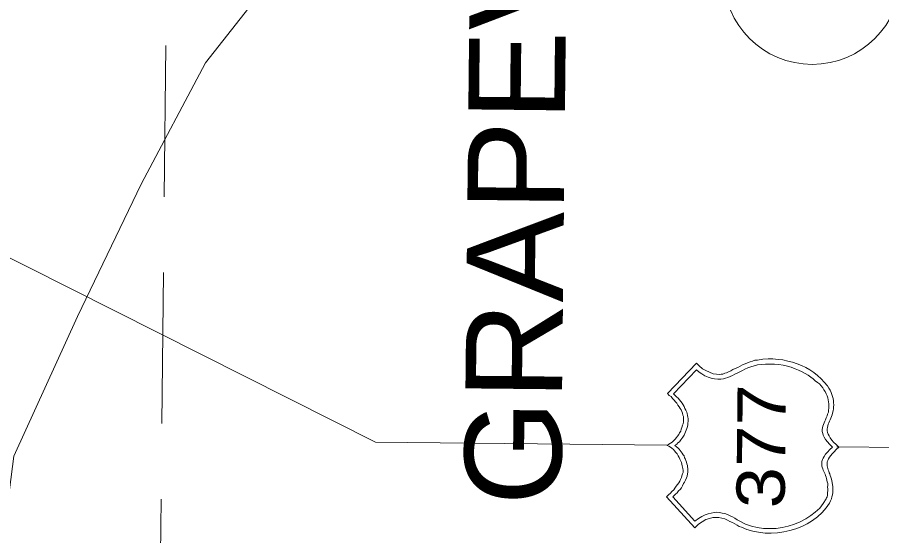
# Model space of a CAD drawing. Extents: x 2356576 to 2377878, y 6966390 to 6990634.
# Drawn here: x 2365706.5 to 2365828.3, y 6968964.1 to 6969037.2 of the extents above; entities that cross this region are included whole.
import ezdxf

# ---------------------------------------------------------------- set-up
doc = ezdxf.new("R2010")
doc.units = 0
doc.header["$LTSCALE"] = 7.1
doc.linetypes.add('MEDIUM_DASHED', pattern=[4.5, 3, -1.5])
doc.layers.add('19', color=7, linetype='Continuous', lineweight=13)
doc.layers.add('8', color=7, linetype='Continuous', lineweight=13)

msp = doc.modelspace()

# ---------------------------------------------------------------- linework, layer by layer
at = {"layer": '19', "linetype": 'MEDIUM_DASHED'}
msp.add_line((2365729.713, 6969256.812), (2365723.521, 6968659.188), dxfattribs=at)
at = {"layer": '19'}
for p, q in [((2365798.008, 6968976.87), (2365756.939, 6968977.295)), ((2365880.416, 6968976.016), (2365821.947, 6968976.622))]:
    msp.add_line(p, q, dxfattribs=at)
for points in [[(2365671.692, 6968744.602), (2365665.266, 6968758.801), (2365663.004, 6968777.877), (2365673.065, 6968799.226), (2365674.476, 6968813.793), (2365683.996, 6968831.843), (2365690.393, 6968844.289), (2365694.525, 6968855.019), (2365697.561, 6968870.136), (2365698.861, 6968882.424), (2365699.629, 6968898.62), (2365699.105, 6968917.587), (2365702.415, 6968941.706), (2365703.658, 6968957.414), (2365705.971, 6968975.299), (2365714.94, 6968994.979), (2365723.922, 6969013.667), (2365732.979, 6969030.738), (2365748.18, 6969050.082), (2365757.827, 6969063.09), (2365768.013, 6969079.038), (2365777.26, 6969088.122)], [(2365756.939, 6968977.295), (2365683.335, 6969014.359), (2365601.496, 6969032.7)], [(2365801.94, 6968965.216), (2365797.961, 6968969.606), (2365798.236, 6968969.843), (2365798.506, 6968970.08), (2365798.721, 6968970.35), (2365798.963, 6968970.587), (2365799.146, 6968970.825), (2365799.329, 6968971.092), (2365799.511, 6968971.302), (2365799.694, 6968971.568), (2365799.844, 6968971.806), (2365799.939, 6968972.045), (2365800.061, 6968972.316), (2365800.124, 6968972.555), (2365800.215, 6968972.823), (2365800.281, 6968973.034), (2365800.284, 6968973.302), (2365800.254, 6968973.574), (2365800.224, 6968973.754), (2365800.138, 6968973.963), (2365800.109, 6968974.204), (2365800.051, 6968974.444), (2365799.934, 6968974.69), (2365799.848, 6968974.898), (2365799.731, 6968975.14), (2365799.613, 6968975.381), (2365799.436, 6968975.623), (2365799.286, 6968975.836), (2365799.08, 6968976.046), (2365798.962, 6968976.26), (2365798.724, 6968976.442), (2365798.514, 6968976.592), (2365798.275, 6968976.715), (2365798.036, 6968976.837), (2365798.278, 6968976.987), (2365798.519, 6968977.164), (2365798.761, 6968977.31), (2365798.975, 6968977.52), (2365799.185, 6968977.697), (2365799.34, 6968977.936), (2365799.522, 6968978.142), (2365799.672, 6968978.38), (2365799.795, 6968978.619), (2365799.949, 6968978.858), (2365800.04, 6968979.129), (2365800.134, 6968979.368), (2365800.197, 6968979.667), (2365800.288, 6968979.874), (2365800.355, 6968980.173), (2365800.358, 6968980.445), (2365800.36, 6968980.653), (2365800.362, 6968980.893), (2365800.272, 6968981.106), (2365800.215, 6968981.375), (2365800.097, 6968981.588), (2365800.008, 6968981.829), (2365799.862, 6968982.039), (2365799.745, 6968982.28), (2365799.567, 6968982.494), (2365799.39, 6968982.764), (2365799.212, 6968982.977), (2365799.034, 6968983.219), (2365798.796, 6968983.43), (2365798.587, 6968983.704), (2365798.349, 6968983.886), (2365798.112, 6968984.129), (2365802.18, 6968988.435), (2365802.564, 6968988.043), (2365803.012, 6968987.646), (2365803.517, 6968987.373), (2365804.027, 6968987.156), (2365804.533, 6968986.943), (2365805.012, 6968986.878), (2365805.404, 6968986.841), (2365805.672, 6968986.871), (2365805.913, 6968986.896), (2365806.154, 6968987.014), (2365806.427, 6968987.071), (2365806.696, 6968987.22), (2365806.998, 6968987.365), (2365807.299, 6968987.514), (2365807.633, 6968987.658), (2365807.995, 6968987.835), (2365808.324, 6968988.011), (2365808.658, 6968988.188), (2365809.048, 6968988.336), (2365809.381, 6968988.48), (2365809.743, 6968988.629), (2365810.072, 6968988.713), (2365810.405, 6968988.83), (2365810.765, 6968988.858), (2365811.514, 6968988.97), (2365812.267, 6968989.023), (2365812.955, 6968989.015), (2365813.674, 6968988.948), (2365814.366, 6968988.881), (2365815.052, 6968988.722), (2365815.711, 6968988.567), (2365816.368, 6968988.348), (2365816.998, 6968988.101), (2365817.595, 6968987.795)], [(2365818.626, 6968986.224), (2365818.301, 6968986.468), (2365817.912, 6968986.744), (2365817.494, 6968986.956), (2365817.048, 6968987.201), (2365816.571, 6968987.418), (2365816.061, 6968987.631), (2365815.523, 6968987.849), (2365814.985, 6968988.002), (2365814.386, 6968988.129), (2365813.787, 6968988.227), (2365813.188, 6968988.293), (2365812.56, 6968988.299), (2365811.899, 6968988.274), (2365811.327, 6968988.22), (2365810.786, 6968988.166), (2365810.305, 6968988.051), (2365809.855, 6968987.907), (2365809.434, 6968987.76), (2365809.012, 6968987.584), (2365808.65, 6968987.408), (2365808.288, 6968987.204), (2365807.926, 6968986.995), (2365807.592, 6968986.851), (2365807.262, 6968986.674), (2365806.929, 6968986.526), (2365806.599, 6968986.381), (2365806.266, 6968986.293), (2365805.966, 6968986.208), (2365805.605, 6968986.151), (2365805.185, 6968986.156), (2365804.706, 6968986.221), (2365804.259, 6968986.313), (2365803.808, 6968986.438), (2365803.362, 6968986.623), (2365802.945, 6968986.899), (2365802.555, 6968987.171), (2365802.17, 6968987.475), (2365798.951, 6968984.088), (2365799.161, 6968983.878), (2365799.367, 6968983.696), (2365799.605, 6968983.481), (2365799.783, 6968983.272), (2365799.96, 6968983.03), (2365800.138, 6968982.788), (2365800.287, 6968982.546), (2365800.437, 6968982.305), (2365800.554, 6968982.031), (2365800.699, 6968981.79), (2365800.817, 6968981.521), (2365800.875, 6968981.308), (2365800.932, 6968981.04), (2365800.962, 6968980.827), (2365801.02, 6968980.647), (2365801.018, 6968980.439), (2365801.015, 6968980.227), (2365800.981, 6968979.959), (2365800.95, 6968979.719), (2365800.916, 6968979.48), (2365800.825, 6968979.209), (2365800.731, 6968979.001), (2365800.64, 6968978.73), (2365800.517, 6968978.492), (2365800.423, 6968978.285), (2365800.268, 6968977.986), (2365800.118, 6968977.808), (2365799.964, 6968977.597), (2365799.782, 6968977.359), (2365799.572, 6968977.213), (2365799.39, 6968977.003), (2365799.116, 6968976.826), (2365799.354, 6968976.644), (2365799.565, 6968976.493), (2365799.742, 6968976.28), (2365799.888, 6968976.098), (2365800.039, 6968975.916), (2365800.157, 6968975.735), (2365800.306, 6968975.494), (2365800.453, 6968975.344), (2365800.51, 6968975.104), (2365800.628, 6968974.89), (2365800.686, 6968974.682), (2365800.776, 6968974.469), (2365800.801, 6968974.256), (2365800.891, 6968974.016), (2365800.917, 6968973.807), (2365800.947, 6968973.595), (2365800.972, 6968973.355), (2365800.969, 6968973.055), (2365800.907, 6968972.815), (2365800.843, 6968972.516), (2365800.753, 6968972.249), (2365800.63, 6968971.95), (2365800.506, 6968971.651), (2365800.352, 6968971.441), (2365800.197, 6968971.143), (2365800.046, 6968970.876), (2365799.864, 6968970.638), (2365799.65, 6968970.428), (2365799.467, 6968970.162), (2365799.225, 6968969.953)], [(2365817.595, 6968987.795), (2365818.159, 6968987.461), (2365818.695, 6968987.096), (2365819.231, 6968986.698), (2365819.738, 6968986.213), (2365820.181, 6968985.728), (2365820.628, 6968985.216), (2365820.833, 6968984.914), (2365821.01, 6968984.612), (2365821.159, 6968984.31), (2365821.244, 6968984.009), (2365821.361, 6968983.736), (2365821.418, 6968983.435), (2365821.474, 6968983.107), (2365821.503, 6968982.835), (2365821.528, 6968982.534), (2365821.497, 6968982.235), (2365821.494, 6968981.967), (2365821.432, 6968981.695), (2365821.337, 6968981.396), (2365821.306, 6968981.156), (2365821.212, 6968980.917), (2365821.121, 6968980.678), (2365821.027, 6968980.439), (2365820.936, 6968980.232), (2365820.814, 6968980.021), (2365820.752, 6968979.814), (2365820.69, 6968979.603), (2365820.627, 6968979.363), (2365820.593, 6968979.156), (2365820.591, 6968978.916), (2365820.648, 6968978.675), (2365820.738, 6968978.434), (2365820.883, 6968978.161), (2365821.032, 6968977.919), (2365821.269, 6968977.589), (2365821.506, 6968977.286), (2365821.863, 6968976.982), (2365822.247, 6968976.586), (2365821.883, 6968976.262), (2365821.58, 6968975.933), (2365821.277, 6968975.668), (2365821.094, 6968975.398), (2365820.912, 6968975.16), (2365820.761, 6968974.922), (2365820.699, 6968974.714), (2365820.605, 6968974.503), (2365820.575, 6968974.324), (2365820.573, 6968974.112), (2365820.599, 6968973.963), (2365820.657, 6968973.751), (2365820.687, 6968973.57), (2365820.746, 6968973.39), (2365820.831, 6968973.181), (2365820.889, 6968972.968), (2365820.98, 6968972.819), (2365821.037, 6968972.579), (2365821.123, 6968972.338), (2365821.212, 6968972.097), (2365821.237, 6968971.825), (2365821.295, 6968971.584), (2365821.352, 6968971.283), (2365821.381, 6968971.043), (2365821.378, 6968970.743), (2365821.376, 6968970.503), (2365821.373, 6968970.203), (2365821.337, 6968969.876), (2365821.246, 6968969.604), (2365821.183, 6968969.305), (2365821.06, 6968969.006), (2365820.905, 6968968.708), (2365820.45, 6968968.025), (2365819.871, 6968967.371), (2365819.237, 6968966.777), (2365818.539, 6968966.244), (2365817.786, 6968965.772), (2365817.03, 6968965.388), (2365816.187, 6968965.097), (2365815.317, 6968964.838), (2365814.475, 6968964.666), (2365813.601, 6968964.523), (2365812.701, 6968964.473), (2365811.833, 6968964.482), (2365810.934, 6968964.583), (2365810.123, 6968964.739), (2365809.286, 6968964.988), (2365808.509, 6968965.296), (2365808.21, 6968965.419), (2365807.912, 6968965.574), (2365807.586, 6968965.758), (2365807.256, 6968965.969), (2365806.898, 6968966.125), (2365806.539, 6968966.309), (2365806.153, 6968966.493), (2365805.762, 6968966.557), (2365805.343, 6968966.649), (2365804.895, 6968966.654), (2365804.475, 6968966.658), (2365803.993, 6968966.515), (2365803.512, 6968966.368), (2365802.969, 6968966.074)], [(2365798.833, 6968969.597), (2365801.949, 6968966.144), (2365802.462, 6968966.531), (2365802.944, 6968966.794), (2365803.399, 6968967.029), (2365803.821, 6968967.205), (2365804.27, 6968967.292), (2365804.662, 6968967.376), (2365805.023, 6968967.432), (2365805.41, 6968967.368), (2365805.801, 6968967.276), (2365806.161, 6968967.213), (2365806.548, 6968967.089), (2365806.906, 6968966.905), (2365807.236, 6968966.749), (2365807.594, 6968966.566), (2365807.92, 6968966.354), (2365808.278, 6968966.139), (2365809.086, 6968965.742), (2365809.923, 6968965.462), (2365810.729, 6968965.245), (2365811.6, 6968965.144), (2365812.499, 6968965.107), (2365813.4, 6968965.126), (2365814.269, 6968965.269), (2365815.111, 6968965.468), (2365815.986, 6968965.731), (2365816.798, 6968966.082), (2365817.582, 6968966.462), (2365818.307, 6968966.935), (2365818.912, 6968967.441), (2365819.55, 6968968.002), (2365820.036, 6968968.629), (2365820.463, 6968969.285), (2365820.493, 6968969.432), (2365820.586, 6968969.583), (2365820.648, 6968969.791), (2365820.651, 6968970.031), (2365820.653, 6968970.211), (2365820.683, 6968970.45), (2365820.686, 6968970.69), (2365820.66, 6968970.931), (2365820.663, 6968971.203), (2365820.665, 6968971.443), (2365820.576, 6968971.684), (2365820.55, 6968971.924), (2365820.521, 6968972.164), (2365820.435, 6968972.373), (2365820.377, 6968972.586), (2365820.319, 6968972.766), (2365820.201, 6968972.975), (2365820.111, 6968973.156), (2365820.025, 6968973.337), (2365819.967, 6968973.518), (2365819.877, 6968973.759), (2365819.851, 6968973.911), (2365819.821, 6968974.119), (2365819.823, 6968974.331), (2365819.857, 6968974.543), (2365819.921, 6968974.842), (2365820.011, 6968975.05), (2365820.193, 6968975.288), (2365820.348, 6968975.586), (2365820.651, 6968975.883), (2365820.955, 6968976.24), (2365821.347, 6968976.568), (2365820.931, 6968976.992), (2365820.635, 6968977.355), (2365820.37, 6968977.658), (2365820.161, 6968977.988), (2365820.044, 6968978.289), (2365819.959, 6968978.53), (2365819.902, 6968978.803), (2365819.904, 6968979.071), (2365819.935, 6968979.311), (2365819.969, 6968979.522), (2365820.06, 6968979.761), (2365820.154, 6968980), (2365820.244, 6968980.239), (2365820.367, 6968980.446), (2365820.461, 6968980.717), (2365820.584, 6968980.984), (2365820.647, 6968981.255), (2365820.77, 6968981.522), (2365820.773, 6968981.822), (2365820.804, 6968982.094), (2365820.839, 6968982.393), (2365820.81, 6968982.694), (2365820.785, 6968982.962), (2365820.756, 6968983.262), (2365820.671, 6968983.535), (2365820.614, 6968983.836), (2365820.437, 6968984.106), (2365820.32, 6968984.407), (2365820.142, 6968984.649), (2365819.965, 6968984.951), (2365819.728, 6968985.225), (2365819.491, 6968985.495), (2365819.253, 6968985.71), (2365818.924, 6968985.953), (2365818.626, 6968986.224)], [(2365799.225, 6968969.953), (2365799.015, 6968969.775), (2365798.833, 6968969.597)], [(2365802.969, 6968966.074), (2365802.453, 6968965.719), (2365801.94, 6968965.216)]]:
    msp.add_lwpolyline(points, dxfattribs=at)
msp.add_circle((2365818.484, 6969043.016), 12.486, dxfattribs=at)
at = {"layer": '8', "linetype": 'MEDIUM_DASHED'}
msp.add_line((2365729.713, 6969256.812), (2365723.521, 6968659.188), dxfattribs=at)
at = {"layer": '8'}
for p, q in [((2365798.008, 6968976.87), (2365756.939, 6968977.295)), ((2365880.416, 6968976.016), (2365821.947, 6968976.622))]:
    msp.add_line(p, q, dxfattribs=at)
for points in [[(2365671.692, 6968744.602), (2365665.266, 6968758.801), (2365663.004, 6968777.877), (2365673.065, 6968799.226), (2365674.476, 6968813.793), (2365683.996, 6968831.843), (2365690.393, 6968844.289), (2365694.525, 6968855.019), (2365697.561, 6968870.136), (2365698.861, 6968882.424), (2365699.629, 6968898.62), (2365699.105, 6968917.587), (2365702.415, 6968941.706), (2365703.658, 6968957.414), (2365705.971, 6968975.299), (2365714.94, 6968994.979), (2365723.922, 6969013.667), (2365732.979, 6969030.738), (2365748.18, 6969050.082), (2365757.827, 6969063.09), (2365768.013, 6969079.038), (2365777.26, 6969088.122)], [(2365756.939, 6968977.295), (2365683.335, 6969014.359), (2365601.496, 6969032.7)], [(2365801.94, 6968965.216), (2365797.961, 6968969.606), (2365798.236, 6968969.843), (2365798.506, 6968970.08), (2365798.721, 6968970.35), (2365798.963, 6968970.587), (2365799.146, 6968970.825), (2365799.329, 6968971.092), (2365799.511, 6968971.302), (2365799.694, 6968971.568), (2365799.844, 6968971.806), (2365799.939, 6968972.045), (2365800.061, 6968972.316), (2365800.124, 6968972.555), (2365800.215, 6968972.823), (2365800.281, 6968973.034), (2365800.284, 6968973.302), (2365800.254, 6968973.574), (2365800.224, 6968973.754), (2365800.138, 6968973.963), (2365800.109, 6968974.204), (2365800.051, 6968974.444), (2365799.934, 6968974.69), (2365799.848, 6968974.898), (2365799.731, 6968975.14), (2365799.613, 6968975.381), (2365799.436, 6968975.623), (2365799.286, 6968975.836), (2365799.08, 6968976.046), (2365798.962, 6968976.26), (2365798.724, 6968976.442), (2365798.514, 6968976.592), (2365798.275, 6968976.715), (2365798.036, 6968976.837), (2365798.278, 6968976.987), (2365798.519, 6968977.164), (2365798.761, 6968977.31), (2365798.975, 6968977.52), (2365799.185, 6968977.697), (2365799.34, 6968977.936), (2365799.522, 6968978.142), (2365799.672, 6968978.38), (2365799.795, 6968978.619), (2365799.949, 6968978.858), (2365800.04, 6968979.129), (2365800.134, 6968979.368), (2365800.197, 6968979.667), (2365800.288, 6968979.874), (2365800.355, 6968980.173), (2365800.358, 6968980.445), (2365800.36, 6968980.653), (2365800.362, 6968980.893), (2365800.272, 6968981.106), (2365800.215, 6968981.375), (2365800.097, 6968981.588), (2365800.008, 6968981.829), (2365799.862, 6968982.039), (2365799.745, 6968982.28), (2365799.567, 6968982.494), (2365799.39, 6968982.764), (2365799.212, 6968982.977), (2365799.034, 6968983.219), (2365798.796, 6968983.43), (2365798.587, 6968983.704), (2365798.349, 6968983.886), (2365798.112, 6968984.129), (2365802.18, 6968988.435), (2365802.564, 6968988.043), (2365803.012, 6968987.646), (2365803.517, 6968987.373), (2365804.027, 6968987.156), (2365804.533, 6968986.943), (2365805.012, 6968986.878), (2365805.404, 6968986.841), (2365805.672, 6968986.871), (2365805.913, 6968986.896), (2365806.154, 6968987.014), (2365806.427, 6968987.071), (2365806.696, 6968987.22), (2365806.998, 6968987.365), (2365807.299, 6968987.514), (2365807.633, 6968987.658), (2365807.995, 6968987.835), (2365808.324, 6968988.011), (2365808.658, 6968988.188), (2365809.048, 6968988.336), (2365809.381, 6968988.48), (2365809.743, 6968988.629), (2365810.072, 6968988.713), (2365810.405, 6968988.83), (2365810.765, 6968988.858), (2365811.514, 6968988.97), (2365812.267, 6968989.023), (2365812.955, 6968989.015), (2365813.674, 6968988.948), (2365814.366, 6968988.881), (2365815.052, 6968988.722), (2365815.711, 6968988.567), (2365816.368, 6968988.348), (2365816.998, 6968988.101), (2365817.595, 6968987.795)], [(2365818.626, 6968986.224), (2365818.301, 6968986.468), (2365817.912, 6968986.744), (2365817.494, 6968986.956), (2365817.048, 6968987.201), (2365816.571, 6968987.418), (2365816.061, 6968987.631), (2365815.523, 6968987.849), (2365814.985, 6968988.002), (2365814.386, 6968988.129), (2365813.787, 6968988.227), (2365813.188, 6968988.293), (2365812.56, 6968988.299), (2365811.899, 6968988.274), (2365811.327, 6968988.22), (2365810.786, 6968988.166), (2365810.305, 6968988.051), (2365809.855, 6968987.907), (2365809.434, 6968987.76), (2365809.012, 6968987.584), (2365808.65, 6968987.408), (2365808.288, 6968987.204), (2365807.926, 6968986.995), (2365807.592, 6968986.851), (2365807.262, 6968986.674), (2365806.929, 6968986.526), (2365806.599, 6968986.381), (2365806.266, 6968986.293), (2365805.966, 6968986.208), (2365805.605, 6968986.151), (2365805.185, 6968986.156), (2365804.706, 6968986.221), (2365804.259, 6968986.313), (2365803.808, 6968986.438), (2365803.362, 6968986.623), (2365802.945, 6968986.899), (2365802.555, 6968987.171), (2365802.17, 6968987.475), (2365798.951, 6968984.088), (2365799.161, 6968983.878), (2365799.367, 6968983.696), (2365799.605, 6968983.481), (2365799.783, 6968983.272), (2365799.96, 6968983.03), (2365800.138, 6968982.788), (2365800.287, 6968982.546), (2365800.437, 6968982.305), (2365800.554, 6968982.031), (2365800.699, 6968981.79), (2365800.817, 6968981.521), (2365800.875, 6968981.308), (2365800.932, 6968981.04), (2365800.962, 6968980.827), (2365801.02, 6968980.647), (2365801.018, 6968980.439), (2365801.015, 6968980.227), (2365800.981, 6968979.959), (2365800.95, 6968979.719), (2365800.916, 6968979.48), (2365800.825, 6968979.209), (2365800.731, 6968979.001), (2365800.64, 6968978.73), (2365800.517, 6968978.492), (2365800.423, 6968978.285), (2365800.268, 6968977.986), (2365800.118, 6968977.808), (2365799.964, 6968977.597), (2365799.782, 6968977.359), (2365799.572, 6968977.213), (2365799.39, 6968977.003), (2365799.116, 6968976.826), (2365799.354, 6968976.644), (2365799.565, 6968976.493), (2365799.742, 6968976.28), (2365799.888, 6968976.098), (2365800.039, 6968975.916), (2365800.157, 6968975.735), (2365800.306, 6968975.494), (2365800.453, 6968975.344), (2365800.51, 6968975.104), (2365800.628, 6968974.89), (2365800.686, 6968974.682), (2365800.776, 6968974.469), (2365800.801, 6968974.256), (2365800.891, 6968974.016), (2365800.917, 6968973.807), (2365800.947, 6968973.595), (2365800.972, 6968973.355), (2365800.969, 6968973.055), (2365800.907, 6968972.815), (2365800.843, 6968972.516), (2365800.753, 6968972.249), (2365800.63, 6968971.95), (2365800.506, 6968971.651), (2365800.352, 6968971.441), (2365800.197, 6968971.143), (2365800.046, 6968970.876), (2365799.864, 6968970.638), (2365799.65, 6968970.428), (2365799.467, 6968970.162), (2365799.225, 6968969.953)], [(2365817.595, 6968987.795), (2365818.159, 6968987.461), (2365818.695, 6968987.096), (2365819.231, 6968986.698), (2365819.738, 6968986.213), (2365820.181, 6968985.728), (2365820.628, 6968985.216), (2365820.833, 6968984.914), (2365821.01, 6968984.612), (2365821.159, 6968984.31), (2365821.244, 6968984.009), (2365821.361, 6968983.736), (2365821.418, 6968983.435), (2365821.474, 6968983.107), (2365821.503, 6968982.835), (2365821.528, 6968982.534), (2365821.497, 6968982.235), (2365821.494, 6968981.967), (2365821.432, 6968981.695), (2365821.337, 6968981.396), (2365821.306, 6968981.156), (2365821.212, 6968980.917), (2365821.121, 6968980.678), (2365821.027, 6968980.439), (2365820.936, 6968980.232), (2365820.814, 6968980.021), (2365820.752, 6968979.814), (2365820.69, 6968979.603), (2365820.627, 6968979.363), (2365820.593, 6968979.156), (2365820.591, 6968978.916), (2365820.648, 6968978.675), (2365820.738, 6968978.434), (2365820.883, 6968978.161), (2365821.032, 6968977.919), (2365821.269, 6968977.589), (2365821.506, 6968977.286), (2365821.863, 6968976.982), (2365822.247, 6968976.586), (2365821.883, 6968976.262), (2365821.58, 6968975.933), (2365821.277, 6968975.668), (2365821.094, 6968975.398), (2365820.912, 6968975.16), (2365820.761, 6968974.922), (2365820.699, 6968974.714), (2365820.605, 6968974.503), (2365820.575, 6968974.324), (2365820.573, 6968974.112), (2365820.599, 6968973.963), (2365820.657, 6968973.751), (2365820.687, 6968973.57), (2365820.746, 6968973.39), (2365820.831, 6968973.181), (2365820.889, 6968972.968), (2365820.98, 6968972.819), (2365821.037, 6968972.579), (2365821.123, 6968972.338), (2365821.212, 6968972.097), (2365821.237, 6968971.825), (2365821.295, 6968971.584), (2365821.352, 6968971.283), (2365821.381, 6968971.043), (2365821.378, 6968970.743), (2365821.376, 6968970.503), (2365821.373, 6968970.203), (2365821.337, 6968969.876), (2365821.246, 6968969.604), (2365821.183, 6968969.305), (2365821.06, 6968969.006), (2365820.905, 6968968.708), (2365820.45, 6968968.025), (2365819.871, 6968967.371), (2365819.237, 6968966.777), (2365818.539, 6968966.244), (2365817.786, 6968965.772), (2365817.03, 6968965.388), (2365816.187, 6968965.097), (2365815.317, 6968964.838), (2365814.475, 6968964.666), (2365813.601, 6968964.523), (2365812.701, 6968964.473), (2365811.833, 6968964.482), (2365810.934, 6968964.583), (2365810.123, 6968964.739), (2365809.286, 6968964.988), (2365808.509, 6968965.296), (2365808.21, 6968965.419), (2365807.912, 6968965.574), (2365807.586, 6968965.758), (2365807.256, 6968965.969), (2365806.898, 6968966.125), (2365806.539, 6968966.309), (2365806.153, 6968966.493), (2365805.762, 6968966.557), (2365805.343, 6968966.649), (2365804.895, 6968966.654), (2365804.475, 6968966.658), (2365803.993, 6968966.515), (2365803.512, 6968966.368), (2365802.969, 6968966.074)], [(2365798.833, 6968969.597), (2365801.949, 6968966.144), (2365802.462, 6968966.531), (2365802.944, 6968966.794), (2365803.399, 6968967.029), (2365803.821, 6968967.205), (2365804.27, 6968967.292), (2365804.662, 6968967.376), (2365805.023, 6968967.432), (2365805.41, 6968967.368), (2365805.801, 6968967.276), (2365806.161, 6968967.213), (2365806.548, 6968967.089), (2365806.906, 6968966.905), (2365807.236, 6968966.749), (2365807.594, 6968966.566), (2365807.92, 6968966.354), (2365808.278, 6968966.139), (2365809.086, 6968965.742), (2365809.923, 6968965.462), (2365810.729, 6968965.245), (2365811.6, 6968965.144), (2365812.499, 6968965.107), (2365813.4, 6968965.126), (2365814.269, 6968965.269), (2365815.111, 6968965.468), (2365815.986, 6968965.731), (2365816.798, 6968966.082), (2365817.582, 6968966.462), (2365818.307, 6968966.935), (2365818.912, 6968967.441), (2365819.55, 6968968.002), (2365820.036, 6968968.629), (2365820.463, 6968969.285), (2365820.493, 6968969.432), (2365820.586, 6968969.583), (2365820.648, 6968969.791), (2365820.651, 6968970.031), (2365820.653, 6968970.211), (2365820.683, 6968970.45), (2365820.686, 6968970.69), (2365820.66, 6968970.931), (2365820.663, 6968971.203), (2365820.665, 6968971.443), (2365820.576, 6968971.684), (2365820.55, 6968971.924), (2365820.521, 6968972.164), (2365820.435, 6968972.373), (2365820.377, 6968972.586), (2365820.319, 6968972.766), (2365820.201, 6968972.975), (2365820.111, 6968973.156), (2365820.025, 6968973.337), (2365819.967, 6968973.518), (2365819.877, 6968973.759), (2365819.851, 6968973.911), (2365819.821, 6968974.119), (2365819.823, 6968974.331), (2365819.857, 6968974.543), (2365819.921, 6968974.842), (2365820.011, 6968975.05), (2365820.193, 6968975.288), (2365820.348, 6968975.586), (2365820.651, 6968975.883), (2365820.955, 6968976.24), (2365821.347, 6968976.568), (2365820.931, 6968976.992), (2365820.635, 6968977.355), (2365820.37, 6968977.658), (2365820.161, 6968977.988), (2365820.044, 6968978.289), (2365819.959, 6968978.53), (2365819.902, 6968978.803), (2365819.904, 6968979.071), (2365819.935, 6968979.311), (2365819.969, 6968979.522), (2365820.06, 6968979.761), (2365820.154, 6968980), (2365820.244, 6968980.239), (2365820.367, 6968980.446), (2365820.461, 6968980.717), (2365820.584, 6968980.984), (2365820.647, 6968981.255), (2365820.77, 6968981.522), (2365820.773, 6968981.822), (2365820.804, 6968982.094), (2365820.839, 6968982.393), (2365820.81, 6968982.694), (2365820.785, 6968982.962), (2365820.756, 6968983.262), (2365820.671, 6968983.535), (2365820.614, 6968983.836), (2365820.437, 6968984.106), (2365820.32, 6968984.407), (2365820.142, 6968984.649), (2365819.965, 6968984.951), (2365819.728, 6968985.225), (2365819.491, 6968985.495), (2365819.253, 6968985.71), (2365818.924, 6968985.953), (2365818.626, 6968986.224)], [(2365799.225, 6968969.953), (2365799.015, 6968969.775), (2365798.833, 6968969.597)], [(2365802.969, 6968966.074), (2365802.453, 6968965.719), (2365801.94, 6968965.216)]]:
    msp.add_lwpolyline(points, dxfattribs=at)
msp.add_circle((2365818.484, 6969043.016), 12.486, dxfattribs=at)

# ---------------------------------------------------------------- texts
at = {"layer": '19'}
for s, height, width, p in [('GRAPEVINE', 13.62, 1.05, (2365783.067, 6968968.292)), ('377', 6.81, 1.15, (2365814.597, 6968967.933))]:
    msp.add_text(s, height=height, rotation=89.406, dxfattribs=dict(at, width=width)).set_placement(p)
at = {"layer": '8'}
for s, height, width, p in [('GRAPEVINE', 13.62, 1.05, (2365783.067, 6968968.292)), ('377', 6.81, 1.15, (2365814.597, 6968967.933))]:
    msp.add_text(s, height=height, rotation=89.406, dxfattribs=dict(at, width=width)).set_placement(p)

doc.saveas('drawing.dxf')
